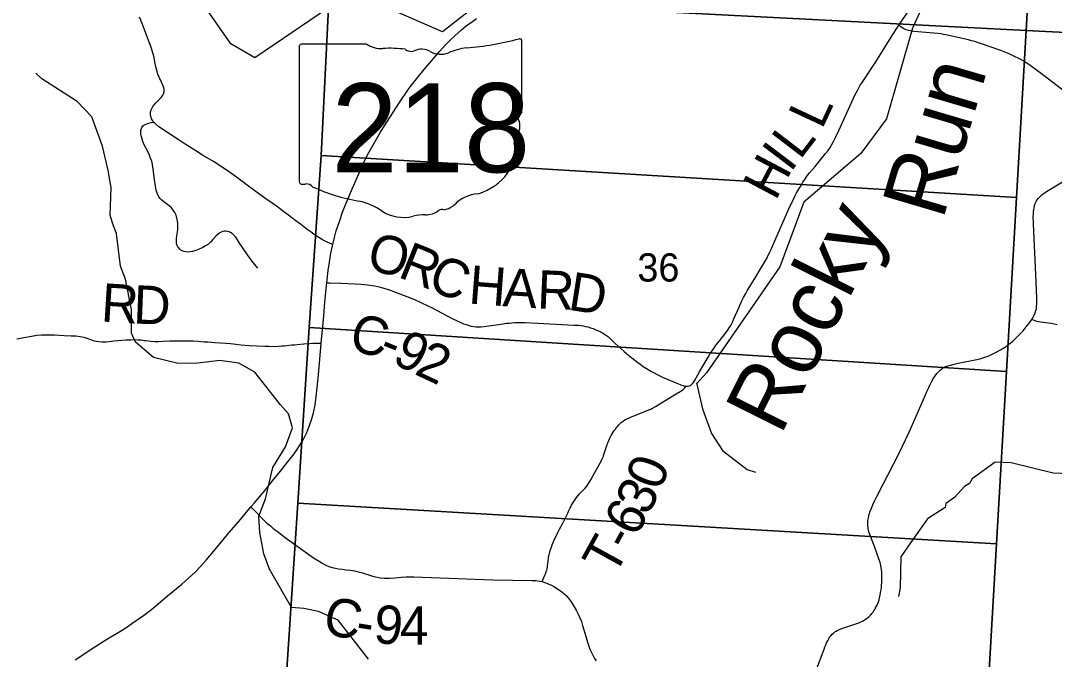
# Model space of a CAD drawing. Extents: x 0 to 34, y 0 to 22.
# Drawn here: x 5.548 to 7.078, y 14.948 to 15.893 of the extents above; entities that cross this region are included whole.
import ezdxf

# ---------------------------------------------------------------- set-up
doc = ezdxf.new("R2010")
doc.units = 0
for name, color, linetype in [('GM_X_County_Road', 7, 'Continuous'), ('GM_X_County_Road_Text', 7, 'Continuous'), ('GM_X_Minor_River', 7, 'Continuous'), ('GM_X_Minor_River_Text', 7, 'Continuous'), ('GM_X_Section', 7, 'Continuous'), ('GM_X_Section_Text', 7, 'Continuous'), ('GM_X_State_Location', 7, 'Continuous'), ('GM_X_State_Route', 7, 'Continuous'), ('GM_X_State_Shield', 7, 'Continuous'), ('GM_X_Township_Road', 7, 'Continuous'), ('GM_X_Township_Road_Text', 7, 'Continuous')]:
    doc.layers.add(name, color=color, linetype=linetype)

msp = doc.modelspace()

# ---------------------------------------------------------------- linework, layer by layer
at = {"layer": 'GM_X_County_Road'}
for points in [[(5.9593, 15.5941), (5.9577, 15.5953), (5.9544, 15.5978), (5.9525, 15.5992), (5.9497, 15.6014), (5.9447, 15.6052), (5.9359, 15.6117), (5.9283, 15.6173), (5.9207, 15.6228), (5.9114, 15.6294), (5.8972, 15.6396), (5.8855, 15.6483), (5.8679, 15.6614), (5.8542, 15.6714), (5.834, 15.6845), (5.8173, 15.6941), (5.8077, 15.7003), (5.7918, 15.7105), (5.7814, 15.7174), (5.7704, 15.7245), (5.759, 15.732), (5.7522, 15.7366), (5.7478, 15.7403), (5.7464, 15.7418), (5.7452, 15.7431), (5.744, 15.7449), (5.7431, 15.7464), (5.7422, 15.748), (5.741, 15.7514), (5.7404, 15.7543), (5.7405, 15.7573), (5.7409, 15.7595), (5.7415, 15.7611), (5.7423, 15.7632), (5.7438, 15.7658), (5.7465, 15.7691), (5.7482, 15.7708), (5.7546, 15.7773), (5.7568, 15.78), (5.7587, 15.7826), (5.76, 15.7849), (5.7602, 15.7857), (5.7605, 15.7867), (5.7608, 15.7884), (5.7609, 15.7912), (5.7605, 15.7937), (5.76, 15.7953), (5.759, 15.7977), (5.7568, 15.8021), (5.7552, 15.8055), (5.7543, 15.8071), (5.7532, 15.8093), (5.7514, 15.8138), (5.7509, 15.8155), (5.7502, 15.8179), (5.7494, 15.8215), (5.7485, 15.825), (5.7475, 15.8298), (5.7467, 15.8353), (5.7453, 15.8405), (5.7422, 15.8517), (5.7406, 15.8564), (5.7388, 15.8615), (5.7329, 15.8772), (5.7282, 15.8887), (5.7241, 15.8984)], [(6.8482, 15.8862), (6.8635, 15.9088)], [(6.0016, 15.505), (6.006, 15.5049), (6.0224, 15.5044), (6.0436, 15.5035), (6.0523, 15.503), (6.0572, 15.5027), (6.0618, 15.5021), (6.0652, 15.5017), (6.0686, 15.5012), (6.0728, 15.5005), (6.0772, 15.4997), (6.0806, 15.4988), (6.0844, 15.4978), (6.0889, 15.4963), (6.0944, 15.4945), (6.1018, 15.4918), (6.124, 15.4832), (6.1321, 15.4798), (6.1387, 15.4769), (6.1438, 15.4745), (6.1479, 15.4725), (6.1522, 15.4704), (6.1564, 15.4683), (6.1871, 15.4524), (6.1943, 15.4486), (6.1998, 15.4462), (6.2038, 15.4445), (6.2076, 15.4432), (6.212, 15.4419), (6.2154, 15.441), (6.2188, 15.4404), (6.2224, 15.44), (6.2263, 15.4398), (6.2301, 15.44), (6.2345, 15.4403), (6.2626, 15.4444), (6.2677, 15.4451), (6.2715, 15.4455), (6.2752, 15.4459), (6.2798, 15.4461), (6.2845, 15.4463), (6.2893, 15.4463), (6.2947, 15.4463), (6.3141, 15.4455), (6.3671, 15.4426), (6.3708, 15.4425), (6.3742, 15.4422), (6.3777, 15.4419), (6.3811, 15.4413), (6.3846, 15.4406), (6.3881, 15.4398), (6.3918, 15.4386), (6.3958, 15.4372), (6.3995, 15.4357), (6.4035, 15.434), (6.4071, 15.4324), (6.4103, 15.4306), (6.4128, 15.429), (6.4155, 15.4271), (6.4184, 15.4249), (6.4215, 15.422), (6.4284, 15.4152), (6.4417, 15.4034), (6.4485, 15.3977), (6.4619, 15.3872), (6.4653, 15.3847), (6.4699, 15.3814), (6.482, 15.3738), (6.4859, 15.3717), (6.4907, 15.3693), (6.4945, 15.3674), (6.4985, 15.3656), (6.5195, 15.3564), (6.5219, 15.3554), (6.5244, 15.3544), (6.5266, 15.3536), (6.5289, 15.3529), (6.53, 15.3525), (6.531, 15.3523), (6.5319, 15.3522), (6.5328, 15.3521), (6.5348, 15.352), (6.5366, 15.3521), (6.5382, 15.3525), (6.5397, 15.353), (6.5409, 15.3539), (6.5419, 15.3548), (6.5429, 15.3559), (6.5439, 15.3571), (6.5448, 15.3584), (6.5459, 15.36), (6.5534, 15.3732), (6.563, 15.39), (6.566, 15.395), (6.5692, 15.4002), (6.572, 15.4046), (6.5744, 15.408), (6.577, 15.4117), (6.5798, 15.4156), (6.5831, 15.4199), (6.5935, 15.4331), (6.5956, 15.4361), (6.5973, 15.4385), (6.5989, 15.441), (6.6004, 15.4439), (6.6019, 15.4469), (6.6036, 15.4506), (6.6112, 15.4682), (6.6133, 15.4731), (6.616, 15.4786), (6.6185, 15.4834), (6.6216, 15.4891), (6.6244, 15.494), (6.635, 15.5116), (6.6445, 15.5272), (6.6531, 15.5422), (6.655, 15.5458), (6.657, 15.5495), (6.6583, 15.5524), (6.6649, 15.567), (6.68, 15.6023), (6.6871, 15.618), (6.6906, 15.6256), (6.6926, 15.6299), (6.6948, 15.6342), (6.697, 15.6382), (6.6994, 15.6424), (6.704, 15.6503), (6.7063, 15.6541), (6.7089, 15.6581), (6.7126, 15.6635), (6.716, 15.6678), (6.7203, 15.673), (6.7242, 15.6774), (6.7399, 15.6963), (6.7436, 15.7011), (6.7466, 15.7056), (6.7491, 15.7099), (6.7516, 15.7143), (6.7545, 15.7201), (6.7595, 15.7305), (6.7764, 15.7674), (6.7833, 15.7826), (6.7852, 15.7864), (6.7869, 15.7898), (6.7891, 15.7937), (6.7912, 15.7974), (6.7938, 15.8016), (6.8144, 15.8321), (6.8371, 15.8685), (6.8482, 15.8862)], [(7.0909, 15.7901), (7.0612, 15.8128), (7.0407, 15.8282), (7.0368, 15.8308), (7.0324, 15.8335), (7.0287, 15.8356), (7.0251, 15.8374), (7.0205, 15.8397), (7.0166, 15.8416), (7.0116, 15.8438), (7.0067, 15.8459), (6.999, 15.8488), (6.9691, 15.8593), (6.9648, 15.8608), (6.9605, 15.8621), (6.9559, 15.8634), (6.9515, 15.8645), (6.9179, 15.8722), (6.9143, 15.8728), (6.9102, 15.8735), (6.906, 15.874), (6.8702, 15.8772), (6.8656, 15.8779), (6.8623, 15.8786), (6.859, 15.8796), (6.8565, 15.8807), (6.8542, 15.8819), (6.8518, 15.8834), (6.8482, 15.8862)], [(6.9156, 15.38), (6.9165, 15.3805), (6.9206, 15.3821), (6.925, 15.3834), (6.9301, 15.3846), (6.936, 15.3859), (6.9638, 15.3915), (6.9699, 15.393), (6.9757, 15.3948), (6.9813, 15.3969), (6.9866, 15.3993), (6.9922, 15.4022), (6.9985, 15.4059), (7.0059, 15.4104), (7.0112, 15.4143), (7.0168, 15.4188), (7.022, 15.4234), (7.0275, 15.4291), (7.0322, 15.4342), (7.0369, 15.4397), (7.0415, 15.4457), (7.0452, 15.451), (7.047, 15.454), (7.0487, 15.4573), (7.0501, 15.4608), (7.0511, 15.464), (7.0518, 15.4671), (7.0522, 15.47), (7.0524, 15.4734), (7.0524, 15.4768), (7.0523, 15.4823), (7.0509, 15.5174), (7.0477, 15.5922), (7.0475, 15.5961), (7.0473, 15.6003), (7.0473, 15.6035), (7.0474, 15.6066), (7.0476, 15.6104), (7.0479, 15.6132), (7.0483, 15.6162), (7.0491, 15.6193), (7.0502, 15.6224), (7.0516, 15.6255), (7.053, 15.6278), (7.0547, 15.63), (7.0564, 15.6318), (7.058, 15.6335), (7.0604, 15.6356), (7.0634, 15.6378), (7.0667, 15.64), (7.0906, 15.6547)], [(6.0104, 15.5618), (6.0063, 15.5633), (6.0011, 15.5656), (5.9953, 15.5687), (5.9842, 15.5757), (5.9782, 15.5799), (5.9726, 15.5842), (5.9675, 15.5881), (5.9626, 15.5918), (5.9593, 15.5941)], [(6.7253, 14.9304), (6.7375, 14.9629), (6.7388, 14.9661), (6.74, 14.9691), (6.7414, 14.9723), (6.7429, 14.9753), (6.7445, 14.9782), (6.7458, 14.9803), (6.7474, 14.9826), (6.7496, 14.9849), (6.7515, 14.9866), (6.7535, 14.9882), (6.7557, 14.9895), (6.758, 14.9907), (6.7606, 14.9919), (6.7638, 14.9932), (6.7862, 15.0008), (6.7892, 15.002), (6.7918, 15.0031), (6.7944, 15.0044), (6.7972, 15.006), (6.7997, 15.0076), (6.8019, 15.0092), (6.8038, 15.0108), (6.8057, 15.0126), (6.8072, 15.0141), (6.8085, 15.0157), (6.81, 15.0175), (6.8114, 15.0196), (6.8128, 15.0217), (6.8139, 15.0238), (6.8152, 15.0262), (6.8161, 15.0281), (6.817, 15.0302), (6.818, 15.0327), (6.819, 15.0358), (6.8198, 15.039), (6.8206, 15.0427), (6.8213, 15.0467), (6.822, 15.0508), (6.8225, 15.0544), (6.8228, 15.0574), (6.8231, 15.0608), (6.8232, 15.0637), (6.8233, 15.0742), (6.8231, 15.0773), (6.8227, 15.0806), (6.8222, 15.0834), (6.8215, 15.0867), (6.8204, 15.0911), (6.8192, 15.0949), (6.8122, 15.1148), (6.8044, 15.135), (6.8034, 15.1386), (6.8027, 15.142), (6.8024, 15.1455), (6.8022, 15.1491), (6.8024, 15.1531), (6.8031, 15.1574), (6.8042, 15.1619), (6.8059, 15.167), (6.8077, 15.1716), (6.8097, 15.1762), (6.8124, 15.182), (6.8157, 15.1887), (6.8248, 15.2069), (6.8476, 15.2511), (6.8634, 15.2838), (6.8877, 15.3393), (6.8902, 15.345), (6.8925, 15.3499), (6.8946, 15.3545), (6.8971, 15.3595), (6.8994, 15.3637), (6.9019, 15.3676), (6.9043, 15.3707), (6.9072, 15.3739), (6.9101, 15.3765), (6.9131, 15.3787), (6.9156, 15.38)], [(5.8893, 15.1733), (5.8915, 15.1711), (5.9089, 15.1532), (5.9125, 15.1498), (5.9148, 15.1478), (5.918, 15.1451), (5.9223, 15.1416), (5.9278, 15.1372), (5.9399, 15.1281), (5.982, 15.0982), (5.9902, 15.0928), (5.9954, 15.0896), (5.9999, 15.0871), (6.0044, 15.0853), (6.0095, 15.0837), (6.0145, 15.0825), (6.019, 15.0818), (6.0244, 15.081), (6.0301, 15.0804), (6.0367, 15.0795), (6.0424, 15.0785), (6.0481, 15.0773), (6.0542, 15.0757), (6.0585, 15.0744), (6.0622, 15.0731), (6.0663, 15.0719), (6.0711, 15.0705), (6.0761, 15.0692), (6.0812, 15.0684), (6.0865, 15.0678), (6.0942, 15.0678), (6.1028, 15.0684), (6.1115, 15.0692), (6.1183, 15.0698), (6.1241, 15.0699), (6.1301, 15.0698), (6.2473, 15.0656), (6.3056, 15.0645), (6.3107, 15.0643), (6.3138, 15.064), (6.3165, 15.0635), (6.3203, 15.0627), (6.3237, 15.0617), (6.3271, 15.0606), (6.3303, 15.0592), (6.3342, 15.0573), (6.3375, 15.0555), (6.3415, 15.0532), (6.3452, 15.0508), (6.349, 15.0479), (6.3526, 15.0451), (6.3558, 15.042), (6.3588, 15.0386), (6.3616, 15.0349), (6.3647, 15.0302), (6.3678, 15.0252), (6.3705, 15.0204), (6.3735, 15.0146), (6.376, 15.0091), (6.3783, 15.0035), (6.3802, 14.9976), (6.3821, 14.9915), (6.3877, 14.9719), (6.3892, 14.9672), (6.3909, 14.9628), (6.3927, 14.9587), (6.3951, 14.9539), (6.3978, 14.9492), (6.4003, 14.9453)]]:
    msp.add_lwpolyline(points, dxfattribs=at)
at = {"layer": 'GM_X_Minor_River'}
for points in [[(7.0512, 16.383), (7.0307, 16.2989), (7.052, 16.2373), (7.046, 16.2034), (6.9901, 16.1494), (6.9529, 16.0675), (6.8687, 15.8822), (6.8299, 15.7479), (6.7922, 15.6967), (6.7077, 15.6246), (6.6722, 15.5286), (6.5634, 15.372), (6.5491, 15.356)], [(6.4319, 15.9861), (6.3591, 15.951), (6.2556, 15.9417), (6.1729, 15.8768), (6.0775, 15.9181), (6.0039, 15.9121), (5.8952, 15.8379), (5.8596, 15.8588), (5.8201, 15.9154)], [(5.8949, 15.3727), (5.8714, 15.386), (5.8434, 15.3902), (5.8104, 15.3863), (5.7816, 15.3856), (5.7452, 15.3946), (5.7183, 15.4171), (5.7122, 15.4304), (5.7122, 15.4657), (5.7035, 15.5106), (5.696, 15.5296), (5.6903, 15.5779), (5.6857, 15.5896), (5.6808, 15.6045), (5.6824, 15.6463), (5.6789, 15.6653), (5.6786, 15.6695), (5.6695, 15.7075), (5.6536, 15.7508), (5.632, 15.7732), (5.5797, 15.807), (5.5706, 15.8154)], [(6.0634, 14.9479), (6.0181, 15.0056), (5.9894, 15.0186), (5.9676, 15.0231), (5.9491, 15.0245), (5.9168, 15.081), (5.9084, 15.104), (5.9022, 15.1354), (5.901, 15.1597), (5.9109, 15.1852), (5.9214, 15.2316), (5.9404, 15.2625), (5.9507, 15.2906), (5.9449, 15.3113), (5.9329, 15.3246), (5.8948, 15.3728)], [(6.5489, 15.3569), (6.5577, 15.3187), (6.5708, 15.2821), (6.5873, 15.2569), (6.6236, 15.2289), (6.636, 15.225)], [(7.1238, 15.2213), (7.0766, 15.2231), (7.0144, 15.2384), (6.991, 15.2396), (6.9569, 15.2148), (6.9526, 15.2081), (6.9453, 15.2038), (6.9308, 15.1872), (6.918, 15.1785), (6.9167, 15.1724), (6.8905, 15.1558), (6.8656, 15.1201), (6.851, 15.0993), (6.8504, 15.0538), (6.8477, 15.0406)]]:
    msp.add_lwpolyline(points, dxfattribs=at)
at = {"layer": 'GM_X_Section'}
for points in [[(6.3009, 16.0274), (7.0427, 15.9845), (7.0366, 15.8787), (6.2887, 15.9168)], [(4.9568, 15.9843), (6.0049, 15.9328), (5.9932, 15.6936), (5.9754, 15.4391), (5.9587, 15.1787), (5.9407, 14.9107), (5.9405, 14.9074), (4.8777, 14.9601)], [(7.0427, 15.9845), (7.6919, 15.9479), (7.7031, 15.9322), (7.7119, 15.9182), (7.7344, 15.885), (7.7427, 15.8732), (7.7526, 15.86), (7.7602, 15.8494), (7.772, 15.8408), (7.2798, 15.8662), (7.0366, 15.8787)], [(6.0049, 15.9328), (6.2887, 15.9168), (7.0366, 15.8787), (7.0224, 15.6312), (5.9932, 15.6936)], [(7.0366, 15.8787), (7.2798, 15.8662), (7.258, 15.5464), (7.2406, 15.29), (7.2246, 15.0549), (7.21, 14.8415), (6.9776, 14.8549), (6.9928, 15.1186), (7.0075, 15.3738), (7.0224, 15.6312)], [(7.0224, 15.6312), (7.0075, 15.3738), (5.9754, 15.4391), (5.9932, 15.6936)], [(5.9754, 15.4391), (7.0075, 15.3738), (6.9928, 15.1186), (5.9587, 15.1787)], [(6.9928, 15.1186), (6.9776, 14.8549), (5.9407, 14.9107), (5.9587, 15.1787)]]:
    msp.add_lwpolyline(points, close=True, dxfattribs=at)
at = {"layer": 'GM_X_State_Route'}
msp.add_lwpolyline([(5.6289, 14.9471), (5.658, 14.9663), (5.6743, 14.9765), (5.6951, 14.9888), (5.7041, 14.9945), (5.7127, 15.0006), (5.7301, 15.0128), (5.7418, 15.0216), (5.7657, 15.0415), (5.7868, 15.0591), (5.8068, 15.0768), (5.8146, 15.085), (5.8231, 15.0947), (5.8364, 15.1105), (5.8572, 15.1353), (5.8736, 15.1548), (5.8893, 15.1733), (5.8945, 15.1794), (5.9108, 15.1988), (5.9212, 15.2118), (5.9328, 15.2261), (5.9434, 15.2394), (5.953, 15.2521), (5.96, 15.2621), (5.9667, 15.2726), (5.9697, 15.2785), (5.9719, 15.2837), (5.975, 15.2913), (5.9787, 15.3021), (5.9819, 15.3128), (5.9842, 15.3245), (5.9859, 15.3365), (5.9888, 15.3641), (5.9906, 15.386), (5.9917, 15.3975), (5.9932, 15.4155), (5.9948, 15.4312), (5.9964, 15.4503), (5.9988, 15.4758), (6.0012, 15.5015), (6.0016, 15.505), (6.0036, 15.5235), (6.0053, 15.5358), (6.0075, 15.5489), (6.0104, 15.5618), (6.0129, 15.5722), (6.0156, 15.5822), (6.0206, 15.5975), (6.0249, 15.6095), (6.0313, 15.6254), (6.0397, 15.645), (6.0504, 15.6699), (6.057, 15.6844), (6.0637, 15.6981), (6.0714, 15.7119), (6.0815, 15.7291), (6.0959, 15.7514), (6.1083, 15.7706), (6.1236, 15.7932), (6.1269, 15.7978), (6.1346, 15.8077), (6.148, 15.8237), (6.1689, 15.8479), (6.1773, 15.8573), (6.1824, 15.8627), (6.1908, 15.8708), (6.201, 15.8796), (6.2085, 15.8857), (6.215, 15.8906), (6.2233, 15.8964)], dxfattribs=at)
at = {"layer": 'GM_X_State_Shield'}
for p, q in [((5.9607, 15.8547), (5.9607, 15.6546)), ((6.0605, 15.8581), (5.964, 15.8581)), ((6.2903, 15.7584), (6.2903, 15.8631)), ((6.2903, 15.7584), (6.2903, 15.7584))]:
    msp.add_line(p, q, dxfattribs=at)
for centre, major_axis, start_param, end_param in [((6.1729, 16.1309), (0.3495, 0), 4.814394, 5.042369), ((6.2867, 15.8635), (0.00367, 0), 6.141152, 7.989035), ((5.9645, 15.8551), (0.00382, 0), 1.712693, 3.28349), ((6.0835, 15.8813), (0.037, 0), 4.042523, 4.731795), ((6.0958, 15.7458), (0.133, 0), 1.404758, 1.657858), ((6.1416, 15.833), (0.0222, 0), 0.950623, 2.079405), ((6.2175, 15.797), (0.0703, 0), 1.699011, 2.107814), ((6.126, 15.8561), (0.0107, 0), 3.836095, 5.185415), ((6.1703, 15.8647), (0.0267, 0), 4.081561, 5.145723), ((6.2895, 15.7507), (0.00568, 0), 1.883978, 3.671073), ((6.2534, 15.7375), (0.0341, 0), 5.934695, 6.695948), ((6.2864, 15.758), (0.00393, 0), 5.05454, 6.418171), ((6.3035, 15.7146), (0.0248, 0), 2.387724, 3.262537), ((6.1925, 15.7013), (0.0874, 0), 5.101752, 6.440018), ((5.9646, 15.6541), (0.00385, 0), 3.00124, 4.508301), ((5.9651, 15.6746), (0.0294, 0), 4.665946, 4.897461), ((5.9712, 15.643), (0.0106, 0), 0.519207, 1.627899), ((6.105, 15.8228), (0.2524, 0), 4.195997, 4.488961), ((6.0297, 15.5646), (0.079, 0), 0.823519, 1.323587), ((6.1687, 15.6352), (0.0282, 0), 4.937069, 5.64225), ((6.2294, 15.5984), (0.0479, 0), 1.647645, 2.488434), ((6.1151, 15.642), (0.0501, 0), 4.026481, 4.996735), ((6.1441, 15.5728), (0.0412, 0), 1.495662, 1.94098), ((6.1478, 15.627), (0.0267, 0), 4.691044, 5.507374), ((6.1719, 15.6076), (0.00752, 0), 1.147584, 2.315152)]:
    msp.add_ellipse(centre, major_axis=major_axis, ratio=0.8, start_param=start_param, end_param=end_param, dxfattribs=at)
at = {"layer": 'GM_X_Township_Road'}
for points in [[(5.8992, 15.5265), (5.8904, 15.5377), (5.8842, 15.5464), (5.8777, 15.556), (5.8725, 15.5638), (5.8695, 15.5685), (5.8662, 15.5729), (5.8634, 15.5763), (5.8612, 15.5783), (5.8591, 15.5796), (5.8572, 15.5804), (5.8546, 15.581), (5.8519, 15.5814), (5.8501, 15.5814), (5.8476, 15.5809), (5.8453, 15.58), (5.8432, 15.5788), (5.8407, 15.577), (5.8375, 15.574), (5.8329, 15.569), (5.8295, 15.5653), (5.8263, 15.5625), (5.8222, 15.5597), (5.8178, 15.5573), (5.8128, 15.5549), (5.8075, 15.5529), (5.8028, 15.5515), (5.7991, 15.5508), (5.796, 15.5506), (5.7929, 15.5508), (5.7905, 15.5513), (5.7876, 15.5523), (5.7855, 15.5536), (5.7836, 15.5552), (5.7819, 15.5571), (5.7806, 15.5592), (5.7801, 15.5605), (5.7796, 15.5617), (5.7792, 15.5636), (5.779, 15.565), (5.7789, 15.5668), (5.7791, 15.5687), (5.7792, 15.5701), (5.7797, 15.5744), (5.7809, 15.5833), (5.7812, 15.588), (5.7811, 15.5923), (5.7807, 15.5966), (5.7797, 15.6008), (5.7784, 15.605), (5.7765, 15.6089), (5.7742, 15.6126), (5.7714, 15.6159), (5.7683, 15.6189), (5.7604, 15.625), (5.7566, 15.6281), (5.7549, 15.6299), (5.753, 15.6324), (5.7515, 15.6351), (5.7503, 15.638), (5.7491, 15.6422), (5.7479, 15.6483), (5.7466, 15.6581), (5.7447, 15.6735), (5.7436, 15.6803), (5.7424, 15.6851), (5.7408, 15.6898), (5.7384, 15.6954), (5.7342, 15.7037), (5.7314, 15.7092), (5.7292, 15.7143), (5.7275, 15.7196), (5.7267, 15.7226), (5.7261, 15.7263), (5.7261, 15.7294), (5.7264, 15.7312), (5.7271, 15.7335), (5.7279, 15.7352), (5.7294, 15.7372), (5.7307, 15.7385), (5.7328, 15.7396), (5.7349, 15.7404), (5.738, 15.7413), (5.7416, 15.7422), (5.7452, 15.7431)], [(7.0452, 15.451), (7.0484, 15.4496), (7.0504, 15.449), (7.0527, 15.4484), (7.0552, 15.4479), (7.0578, 15.4475), (7.07, 15.4458), (7.0742, 15.4452), (7.0783, 15.4444), (7.0826, 15.4434)], [(5.5425, 15.422), (5.553, 15.4243), (5.5642, 15.4262), (5.5721, 15.4274), (5.5794, 15.428), (5.5868, 15.4283), (5.5917, 15.4281), (5.5985, 15.428), (5.6126, 15.4273), (5.6233, 15.4268), (5.6301, 15.4264), (5.6363, 15.4256), (5.6417, 15.4245), (5.6465, 15.4231), (5.6518, 15.4212), (5.657, 15.4194), (5.6605, 15.4186), (5.6641, 15.418), (5.6689, 15.4177), (5.6748, 15.4179), (5.6862, 15.419), (5.7042, 15.4206), (5.7115, 15.4209), (5.7157, 15.421), (5.7218, 15.4208), (5.7268, 15.4205), (5.7286, 15.4203), (5.7317, 15.4199), (5.7335, 15.4198), (5.7409, 15.4189), (5.7471, 15.4184), (5.7495, 15.4184), (5.7526, 15.4184), (5.7587, 15.4188), (5.7694, 15.4192), (5.7759, 15.4194), (5.7856, 15.4194), (5.7933, 15.4194), (5.7988, 15.4194), (5.8038, 15.4192), (5.8111, 15.4186), (5.8153, 15.4182), (5.8197, 15.4179), (5.8258, 15.4175), (5.8357, 15.4168), (5.8443, 15.4162), (5.8521, 15.4157), (5.8589, 15.4151), (5.867, 15.4143), (5.8744, 15.4135), (5.8867, 15.4123), (5.8979, 15.4116), (5.9096, 15.4112), (5.9158, 15.4111), (5.9245, 15.411), (5.93, 15.4112), (5.9348, 15.4116), (5.9382, 15.412), (5.9425, 15.4124), (5.9498, 15.4131), (5.9541, 15.4135), (5.9578, 15.4139), (5.9676, 15.4148), (5.9757, 15.4153), (5.9809, 15.4156), (5.986, 15.4157), (5.9932, 15.4155)], [(6.3203, 15.0627), (6.3244, 15.0724), (6.3256, 15.0753), (6.3264, 15.0776), (6.3271, 15.0799), (6.3276, 15.0819), (6.328, 15.084), (6.3282, 15.0859), (6.329, 15.0929), (6.3293, 15.0947), (6.3296, 15.0966), (6.3299, 15.0986), (6.3323, 15.1086), (6.3331, 15.1112), (6.3339, 15.1137), (6.3352, 15.1173), (6.3364, 15.1205), (6.3381, 15.1244), (6.3398, 15.1283), (6.3428, 15.1344), (6.3459, 15.1404), (6.3484, 15.1449), (6.3508, 15.1495), (6.3533, 15.1542), (6.3558, 15.1593), (6.3581, 15.1643), (6.3597, 15.1678), (6.3611, 15.1708), (6.3625, 15.1734), (6.3639, 15.176), (6.3653, 15.1785), (6.367, 15.1813), (6.369, 15.1843), (6.3713, 15.1873), (6.3758, 15.1925), (6.3794, 15.1965), (6.3834, 15.2005), (6.3863, 15.2042), (6.389, 15.2078), (6.3923, 15.2133), (6.3959, 15.2198), (6.408, 15.2421), (6.4092, 15.2445), (6.4102, 15.2466), (6.411, 15.2486), (6.4117, 15.2508), (6.4149, 15.2612), (6.4156, 15.263), (6.4163, 15.2652), (6.417, 15.2673), (6.4179, 15.2694), (6.4189, 15.2718), (6.4199, 15.2739), (6.4211, 15.2763), (6.4226, 15.2792), (6.4239, 15.2815), (6.4254, 15.2839), (6.427, 15.2863), (6.4286, 15.2886), (6.4303, 15.2907), (6.4318, 15.2925), (6.4339, 15.2948), (6.4362, 15.2972), (6.4376, 15.2986), (6.4391, 15.2998), (6.4409, 15.3009), (6.4427, 15.3021), (6.4447, 15.3032), (6.4472, 15.3044), (6.4503, 15.3056), (6.4781, 15.3169), (6.481, 15.3182), (6.4837, 15.3196), (6.4881, 15.3222), (6.5162, 15.3393), (6.5269, 15.3457), (6.5284, 15.3466), (6.5297, 15.3476), (6.5306, 15.3486), (6.5314, 15.3497), (6.5328, 15.3521)]]:
    msp.add_lwpolyline(points, dxfattribs=at)

# ---------------------------------------------------------------- texts
at = {"layer": 'GM_X_County_Road_Text'}
for s, rotation, p in [('L', 64.9447, (6.7344, 15.7309)), ('L', 52.5751, (6.7018, 15.6859)), ('I', 52.8936, (6.6878, 15.6674)), ('H', 62.0916, (6.6657, 15.6252)), ('O', 346.1466, (6.0585, 15.5256)), ('R', 338.1479, (6.1051, 15.5143)), ('C', 337.5053, (6.1482, 15.4969)), ('H', 355.5342, (6.2103, 15.4746)), ('A', 356.3425, (6.261, 15.4706)), ('R', 357.5012, (6.3121, 15.4673)), ('D', 351.0036, (6.3571, 15.4655)), ('C', 346.7769, (6.0326, 15.4058)), ('9', 332.8252, (6.0962, 15.3877)), ('-', 337.9181, (6.0758, 15.3959)), ('2', 334.851, (6.1294, 15.3707)), ('C', 348.1983, (5.9934, 14.9866)), ('9', 355.2721, (6.0697, 14.9723)), ('4', 0.07, (6.1098, 14.9692)), ('-', 351.097, (6.0422, 14.9765))]:
    msp.add_text(s, height=0.0568, rotation=rotation, dxfattribs=at).set_placement(p)
at = {"layer": 'GM_X_Minor_River_Text'}
for s, rotation, p in [('Run', 73.5135, (6.9132, 15.5966)), ('Rocky', 63.5135, (6.6733, 15.2777))]:
    msp.add_text(s, height=0.0947, rotation=rotation, dxfattribs=at).set_placement(p)
at = {"layer": 'GM_X_Section_Text'}
msp.add_text('36', height=0.04186, rotation=0, dxfattribs=at).set_placement((6.4612, 15.5069))
at = {"layer": 'GM_X_State_Location'}
for s in ['s', 'r']:
    msp.add_text(s, height=0.000189, dxfattribs=at).set_placement((6.1218, 15.7413))
msp.add_text('218', height=0.000189, rotation=0, dxfattribs=at).set_placement((6.055, 15.7275))
at = {"layer": 'GM_X_State_Shield'}
msp.add_text('218', height=0.13184, dxfattribs=at).set_placement((6.0084, 15.6687))
at = {"layer": 'GM_X_Township_Road_Text'}
for s, rotation, p in [('R', 356.4285, (5.6664, 15.4479)), ('D', 357.7398, (5.7144, 15.4449)), ('0', 68.8146, (6.4952, 15.1958)), ('3', 62.6549, (6.4764, 15.1587)), ('6', 61.4427, (6.4591, 15.1268)), ('T', 61.1593, (6.4272, 15.0688)), ('-', 61.2133, (6.4477, 15.1061))]:
    msp.add_text(s, height=0.0568, rotation=rotation, dxfattribs=at).set_placement(p)

doc.saveas('drawing.dxf')
